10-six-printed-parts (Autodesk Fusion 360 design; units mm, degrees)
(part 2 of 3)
sketch "B Facet 180 Triangle 4" plane through (0, -75, 0) normal (0, -1, 0) x axis (-1, 0, 0)
  line L1 (124, -27.066) -> (60.9665, 27.066)
  line L2 (124, 27.066) -> (124, -27.066)
  line L3 (60.9665, 27.066) -> (124, 27.066)
  line L4 (120, -18.3583) -> (71.7639, 23.066)
  line L5 (120, 23.066) -> (120, -18.3583)
  line L6 (71.7639, 23.066) -> (120, 23.066)
  point P1 (0, 0)
  point P2 (60.9665, 27.066)
  point P3 (124, -27.066)
  point P4 (124, 27.066)
  dimension "d486" distance P1 P2 = 60.9665 (= "Linear Dimension-2")
  dimension "d487" distance P1 P2 = 27.066 (= "Linear Dimension-3")
  dimension "d488" distance P1 P3 = 124 (= "Linear Dimension-4")
  dimension "d489" distance P1 P3 = 27.066 (= "Linear Dimension-5")
  dimension "d490" distance P1 P4 = 124 (= "Linear Dimension-6")
  dimension "d491" distance P1 P4 = 27.066 (= "Linear Dimension-7")
  dimension "d492" = -4 (= "-memberWidth / 2")
extrude "Extrude15" cut sketch "B Facet 180 Triangle 4" profile of L5 L6 L4 against normal blind 4.7 (magnitude of "-( wall + 0.2 mm )")
fillet "Fillet5" radius 1.5 (= "apertureRadius")
work_plane "WorkPlane11" RotateAngle 135 ExtraOffset 0
work_plane "WorkPlane12" AlongDistance 75 (= "bodyWidth / 2") ExtraOffset 0
sketch "B Facet 225 Triangle 1" plane through (0, -53.033, -53.033) normal (0, -0.7071, -0.7071) x axis (1, 0, 0)
  line L1 (23.9949, -27.066) -> (62.2721, 27.066)
  line L2 (0.1814, 27.066) -> (23.9949, -27.066)
  line L3 (62.2721, 27.066) -> (0.1814, 27.066)
  line L4 (24.81, -18.9852) -> (54.5447, 23.066)
  line L5 (6.311, 23.066) -> (24.81, -18.9852)
  line L6 (54.5447, 23.066) -> (6.311, 23.066)
  point P1 (0, 0)
  point P2 (62.2721, 27.066)
  point P3 (23.9949, -27.066)
  point P4 (0.1814, 27.066)
  dimension "d501" distance P1 P2 = 62.2721 (= "Linear Dimension-2")
  dimension "d502" distance P1 P2 = 27.066 (= "Linear Dimension-3")
  dimension "d503" distance P1 P3 = 23.9949 (= "Linear Dimension-4")
  dimension "d504" distance P1 P3 = 27.066 (= "Linear Dimension-5")
  dimension "d505" distance P1 P4 = 0.1814 (= "Linear Dimension-6")
  dimension "d506" distance P1 P4 = 27.066 (= "Linear Dimension-7")
  dimension "d507" = 4 (= "memberWidth / 2")
extrude "Extrude16" cut sketch "B Facet 225 Triangle 1" profile of L5 L6 L4 against normal blind 4.7 (magnitude of "-( wall + 0.2 mm )")
sketch "B Facet 225 Triangle 2" plane through (0, -53.033, -53.033) normal (0, -0.7071, -0.7071) x axis (1, 0, 0)
  line L1 (0.1814, 27.066) -> (23.9949, -27.066)
  line L2 (-74.6684, -27.066) -> (0.1814, 27.066)
  line L3 (23.9949, -27.066) -> (-74.6684, -27.066)
  line L4 (-1.4863, 20.9235) -> (17.8653, -23.066)
  line L5 (-62.3117, -23.066) -> (-1.4863, 20.9235)
  line L6 (17.8653, -23.066) -> (-62.3117, -23.066)
  point P1 (0, 0)
  point P2 (23.9949, -27.066)
  point P3 (0.1814, 27.066)
  point P4 (-74.6684, -27.066)
  dimension "d510" distance P1 P2 = 23.9949 (= "Linear Dimension-2")
  dimension "d511" distance P1 P2 = 27.066 (= "Linear Dimension-3")
  dimension "d512" distance P1 P3 = 0.1814 (= "Linear Dimension-4")
  dimension "d513" distance P1 P3 = 27.066 (= "Linear Dimension-5")
  dimension "d514" distance P1 P4 = 74.6684 (= "Linear Dimension-6")
  dimension "d515" distance P1 P4 = 27.066 (= "Linear Dimension-7")
  dimension "d516" = -4 (= "-memberWidth / 2")
extrude "Extrude17" cut sketch "B Facet 225 Triangle 2" profile of L5 L6 L4 against normal blind 4.7 (magnitude of "-( wall + 0.2 mm )")
sketch "B Facet 225 Triangle 3" plane through (0, -53.033, -53.033) normal (0, -0.7071, -0.7071) x axis (1, 0, 0)
  line L1 (-74.6684, -27.066) -> (0.1814, 27.066)
  line L2 (-124, 27.066) -> (-74.6684, -27.066)
  line L3 (0.1814, 27.066) -> (-124, 27.066)
  line L4 (-74.1179, -21.7315) -> (-12.1753, 23.066)
  line L5 (-114.9429, 23.066) -> (-74.1179, -21.7315)
  line L6 (-12.1753, 23.066) -> (-114.9429, 23.066)
  point P1 (0, 0)
  point P2 (0.1814, 27.066)
  point P3 (-74.6684, -27.066)
  point P4 (-124, 27.066)
  dimension "d519" distance P1 P2 = 0.1814 (= "Linear Dimension-2")
  dimension "d520" distance P1 P2 = 27.066 (= "Linear Dimension-3")
  dimension "d521" distance P1 P3 = 74.6684 (= "Linear Dimension-4")
  dimension "d522" distance P1 P3 = 27.066 (= "Linear Dimension-5")
  dimension "d523" distance P1 P4 = 124 (= "Linear Dimension-6")
  dimension "d524" distance P1 P4 = 27.066 (= "Linear Dimension-7")
  dimension "d525" = 4 (= "memberWidth / 2")
extrude "Extrude18" cut sketch "B Facet 225 Triangle 3" profile of L5 L6 L4 against normal blind 4.7 (magnitude of "-( wall + 0.2 mm )")
sketch "B Facet 225 Triangle 4" plane through (0, -53.033, -53.033) normal (0, -0.7071, -0.7071) x axis (1, 0, 0)
  line L1 (-124, 27.066) -> (-74.6684, -27.066)
  line L2 (-124, -27.066) -> (-124, 27.066)
  line L3 (-74.6684, -27.066) -> (-124, -27.066)
  line L4 (-120, 16.7383) -> (-83.7255, -23.066)
  line L5 (-120, -23.066) -> (-120, 16.7383)
  line L6 (-83.7255, -23.066) -> (-120, -23.066)
  point P1 (0, 0)
  point P2 (-74.6684, -27.066)
  point P3 (-124, 27.066)
  point P4 (-124, -27.066)
  dimension "d528" distance P1 P2 = 74.6684 (= "Linear Dimension-2")
  dimension "d529" distance P1 P2 = 27.066 (= "Linear Dimension-3")
  dimension "d530" distance P1 P3 = 124 (= "Linear Dimension-4")
  dimension "d531" distance P1 P3 = 27.066 (= "Linear Dimension-5")
  dimension "d532" distance P1 P4 = 124 (= "Linear Dimension-6")
  dimension "d533" distance P1 P4 = 27.066 (= "Linear Dimension-7")
  dimension "d534" = -4 (= "-memberWidth / 2")
extrude "Extrude19" cut sketch "B Facet 225 Triangle 4" profile of L5 L6 L4 against normal blind 4.7 (magnitude of "-( wall + 0.2 mm )")
fillet "Fillet6" radius 1.5 (= "apertureRadius")
work_plane "WorkPlane13" RotateAngle 180 ExtraOffset 0
work_plane "WorkPlane14" AlongDistance 75 (= "bodyWidth / 2") ExtraOffset 0
sketch "B Facet 270 Triangle 1" plane through (0, 0, -75) normal (0, 0, -1) x axis (-1, 0, 0)
  line L1 (36.9655, 27.066) -> (-17.1665, -27.066)
  line L2 (53.4167, -27.066) -> (36.9655, 27.066)
  line L3 (-17.1665, -27.066) -> (53.4167, -27.066)
  line L4 (35.0777, 19.5214) -> (-7.5097, -23.066)
  line L5 (48.0205, -23.066) -> (35.0777, 19.5214)
  line L6 (-7.5097, -23.066) -> (48.0205, -23.066)
  point P1 (0, 0)
  point P2 (-17.1665, -27.066)
  point P3 (36.9655, 27.066)
  point P4 (53.4167, -27.066)
  dimension "d543" distance P1 P2 = 17.1665 (= "Linear Dimension-2")
  dimension "d544" distance P1 P2 = 27.066 (= "Linear Dimension-3")
  dimension "d545" distance P1 P3 = 36.9655 (= "Linear Dimension-4")
  dimension "d546" distance P1 P3 = 27.066 (= "Linear Dimension-5")
  dimension "d547" distance P1 P4 = 53.4167 (= "Linear Dimension-6")
  dimension "d548" distance P1 P4 = 27.066 (= "Linear Dimension-7")
  dimension "d549" = 4 (= "memberWidth / 2")
extrude "Extrude20" cut sketch "B Facet 270 Triangle 1" profile of L5 L6 L4 against normal blind 4.7 (magnitude of "-( wall + 0.2 mm )")
sketch "B Facet 270 Triangle 2" plane through (0, 0, -75) normal (0, 0, -1) x axis (-1, 0, 0)
  line L1 (53.4167, -27.066) -> (36.9655, 27.066)
  line L2 (124, 27.066) -> (53.4167, -27.066)
  line L3 (36.9655, 27.066) -> (124, 27.066)
  line L4 (55.5648, -20.3777) -> (42.3618, 23.066)
  line L5 (112.2115, 23.066) -> (55.5648, -20.3777)
  line L6 (42.3618, 23.066) -> (112.2115, 23.066)
  point P1 (0, 0)
  point P2 (36.9655, 27.066)
  point P3 (53.4167, -27.066)
  point P4 (124, 27.066)
  dimension "d552" distance P1 P2 = 36.9655 (= "Linear Dimension-2")
  dimension "d553" distance P1 P2 = 27.066 (= "Linear Dimension-3")
  dimension "d554" distance P1 P3 = 53.4167 (= "Linear Dimension-4")
  dimension "d555" distance P1 P3 = 27.066 (= "Linear Dimension-5")
  dimension "d556" distance P1 P4 = 124 (= "Linear Dimension-6")
  dimension "d557" distance P1 P4 = 27.066 (= "Linear Dimension-7")
  dimension "d558" = -4 (= "-memberWidth / 2")
extrude "Extrude21" cut sketch "B Facet 270 Triangle 2" profile of L5 L6 L4 against normal blind 4.7 (magnitude of "-( wall + 0.2 mm )")
sketch "B Facet 270 Triangle 3" plane through (0, 0, -75) normal (0, 0, -1) x axis (-1, 0, 0)
  line L1 (124, 27.066) -> (53.4167, -27.066)
  line L2 (124, -27.066) -> (124, 27.066)
  line L3 (53.4167, -27.066) -> (124, -27.066)
  line L4 (120, 18.9574) -> (65.2053, -23.066)
  line L5 (120, -23.066) -> (120, 18.9574)
  line L6 (65.2053, -23.066) -> (120, -23.066)
  point P1 (0, 0)
  point P2 (53.4167, -27.066)
  point P3 (124, 27.066)
  point P4 (124, -27.066)
  dimension "d561" distance P1 P2 = 53.4167 (= "Linear Dimension-2")
  dimension "d562" distance P1 P2 = 27.066 (= "Linear Dimension-3")
  dimension "d563" distance P1 P3 = 124 (= "Linear Dimension-4")
  dimension "d564" distance P1 P3 = 27.066 (= "Linear Dimension-5")
  dimension "d565" distance P1 P4 = 124 (= "Linear Dimension-6")
  dimension "d566" distance P1 P4 = 27.066 (= "Linear Dimension-7")
  dimension "d567" = 4 (= "memberWidth / 2")
extrude "Extrude22" cut sketch "B Facet 270 Triangle 3" profile of L5 L6 L4 against normal blind 4.7 (magnitude of "-( wall + 0.2 mm )")
fillet "Fillet7" radius 1.5 (= "apertureRadius")
work_plane "WorkPlane15" RotateAngle 225 ExtraOffset 0
work_plane "WorkPlane16" AlongDistance 75 (= "bodyWidth / 2") ExtraOffset 0
sketch "B Facet 315 Triangle 1" plane through (0, 53.033, -53.033) normal (0, 0.7071, -0.7071) x axis (1, 0, 0)
  line L1 (-82.0711, -27.066) -> (-43.7939, 27.066)
  line L2 (-124, 27.066) -> (-82.0711, -27.066)
  line L3 (-43.7939, 27.066) -> (-124, 27.066)
  line L4 (-82.2175, -20.3449) -> (-51.5213, 23.066)
  line L5 (-115.8422, 23.066) -> (-82.2175, -20.3449)
  line L6 (-51.5213, 23.066) -> (-115.8422, 23.066)
  point P1 (0, 0)
  point P2 (-43.7939, 27.066)
  point P3 (-82.0711, -27.066)
  point P4 (-124, 27.066)
  dimension "d576" distance P1 P2 = 43.7939 (= "Linear Dimension-2")
  dimension "d577" distance P1 P2 = 27.066 (= "Linear Dimension-3")
  dimension "d578" distance P1 P3 = 82.0711 (= "Linear Dimension-4")
  dimension "d579" distance P1 P3 = 27.066 (= "Linear Dimension-5")
  dimension "d580" distance P1 P4 = 124 (= "Linear Dimension-6")
  dimension "d581" distance P1 P4 = 27.066 (= "Linear Dimension-7")
  dimension "d582" = 4 (= "memberWidth / 2")
extrude "Extrude23" cut sketch "B Facet 315 Triangle 1" profile of L5 L6 L4 against normal blind 4.7 (magnitude of "-( wall + 0.2 mm )")
sketch "B Facet 315 Triangle 2" plane through (0, 53.033, -53.033) normal (0, 0.7071, -0.7071) x axis (1, 0, 0)
  line L1 (-124, 27.066) -> (-82.0711, -27.066)
  line L2 (-124, -27.066) -> (-124, 27.066)
  line L3 (-82.0711, -27.066) -> (-124, -27.066)
  line L4 (-120, 15.3697) -> (-90.2289, -23.066)
  line L5 (-120, -23.066) -> (-120, 15.3697)
  line L6 (-90.2289, -23.066) -> (-120, -23.066)
  point P1 (0, 0)
  point P2 (-82.0711, -27.066)
  point P3 (-124, 27.066)
  point P4 (-124, -27.066)
  dimension "d585" distance P1 P2 = 82.0711 (= "Linear Dimension-2")
  dimension "d586" distance P1 P2 = 27.066 (= "Linear Dimension-3")
  dimension "d587" distance P1 P3 = 124 (= "Linear Dimension-4")
  dimension "d588" distance P1 P3 = 27.066 (= "Linear Dimension-5")
  dimension "d589" distance P1 P4 = 124 (= "Linear Dimension-6")
  dimension "d590" distance P1 P4 = 27.066 (= "Linear Dimension-7")
  dimension "d591" = -4 (= "-memberWidth / 2")
extrude "Extrude24" cut sketch "B Facet 315 Triangle 2" profile of L5 L6 L4 against normal blind 4.7 (magnitude of "-( wall + 0.2 mm )")
fillet "Fillet8" radius 1.5 (= "apertureRadius")
work_plane "WorkPlane17" AlongDistance 0.5 (= "qFront") ExtraOffset 0
sketch "A Central Carrier sketch" plane through (0.3536, 0.3536, 0) normal (0.7071, 0.7071, 0) x axis (0, 0, 1)
  circle C1 centre (0, 0) radius 26
  dimension "d598" diameter C1 = 52 (= "carrierOD")
extrude "Extrude25" new body sketch "A Central Carrier sketch" along normal blind 18 (= "spokeDepth")
work_plane "WorkPlane18" AlongDistance 0.5 (= "qFront") ExtraOffset 0
sketch "A Spoke 1 Profile" plane through (0.3536, 0.3536, 0) normal (0.7071, 0.7071, 0) x axis (0, 0, 1)
  line L1 (37.3643, -145.3579) -> (-4.7984, -1.4054)
  line L2 (46.9611, -142.547) -> (37.3643, -145.3579)
  line L3 (4.7984, 1.4054) -> (46.9611, -142.547)
  line L4 (-4.7984, -1.4054) -> (4.7984, 1.4054)
  point P1 (0, 0)
  point P2 (-4.7984, -1.4054)
  point P3 (37.3643, -145.3579)
  point P4 (46.9611, -142.547)
  point P5 (4.7984, 1.4054)
  dimension "d603" distance P1 P2 = 4.7984 (= "Linear Dimension-2")
  dimension "d604" distance P1 P2 = 1.4054 (= "Linear Dimension-3")
  dimension "d605" distance P1 P3 = 37.3643 (= "Linear Dimension-4")
  dimension "d606" distance P1 P3 = 145.3579 (= "Linear Dimension-5")
  dimension "d607" distance P1 P4 = 46.9611 (= "Linear Dimension-6")
  dimension "d608" distance P1 P4 = 142.547 (= "Linear Dimension-7")
  dimension "d609" distance P1 P5 = 4.7984 (= "Linear Dimension-8")
  dimension "d610" distance P1 P5 = 1.4054 (= "Linear Dimension-9")
extrude "Extrude26" add sketch "A Spoke 1 Profile" along normal blind 18 (= "spokeDepth")
sketch "A Spoke 2 Profile" plane through (0.3536, 0.3536, 0) normal (0.7071, 0.7071, 0) x axis (0, 0, 1)
  line L1 (126.9012, -80.1317) -> (-2.5272, -4.3143)
  line L2 (131.9557, -71.5031) -> (126.9012, -80.1317)
  line L3 (2.5272, 4.3143) -> (131.9557, -71.5031)
  line L4 (-2.5272, -4.3143) -> (2.5272, 4.3143)
  point P1 (0, 0)
  point P2 (-2.5272, -4.3143)
  point P3 (126.9012, -80.1317)
  point P4 (131.9557, -71.5031)
  point P5 (2.5272, 4.3143)
  dimension "d613" distance P1 P2 = 2.5272 (= "Linear Dimension-2")
  dimension "d614" distance P1 P2 = 4.3143 (= "Linear Dimension-3")
  dimension "d615" distance P1 P3 = 126.9012 (= "Linear Dimension-4")
  dimension "d616" distance P1 P3 = 80.1317 (= "Linear Dimension-5")
  dimension "d617" distance P1 P4 = 131.9557 (= "Linear Dimension-6")
  dimension "d618" distance P1 P4 = 71.5031 (= "Linear Dimension-7")
  dimension "d619" distance P1 P5 = 2.5272 (= "Linear Dimension-8")
  dimension "d620" distance P1 P5 = 4.3143 (= "Linear Dimension-9")
extrude "Extrude27" add sketch "A Spoke 2 Profile" along normal blind 18 (= "spokeDepth")
sketch "A Spoke 3 Profile" plane through (0.3536, 0.3536, 0) normal (0.7071, 0.7071, 0) x axis (0, 0, 1)
  line L1 (131.9557, 71.5031) -> (2.5272, -4.3143)
  line L2 (126.9012, 80.1317) -> (131.9557, 71.5031)
  line L3 (-2.5272, 4.3143) -> (126.9012, 80.1317)
  line L4 (2.5272, -4.3143) -> (-2.5272, 4.3143)
  point P1 (0, 0)
  point P2 (2.5272, -4.3143)
  point P3 (131.9557, 71.5031)
  point P4 (126.9012, 80.1317)
  point P5 (-2.5272, 4.3143)
  dimension "d623" distance P1 P2 = 2.5272 (= "Linear Dimension-2")
  dimension "d624" distance P1 P2 = 4.3143 (= "Linear Dimension-3")
  dimension "d625" distance P1 P3 = 131.9557 (= "Linear Dimension-4")
  dimension "d626" distance P1 P3 = 71.5031 (= "Linear Dimension-5")
  dimension "d627" distance P1 P4 = 126.9012 (= "Linear Dimension-6")
  dimension "d628" distance P1 P4 = 80.1317 (= "Linear Dimension-7")
  dimension "d629" distance P1 P5 = 2.5272 (= "Linear Dimension-8")
  dimension "d630" distance P1 P5 = 4.3143 (= "Linear Dimension-9")
extrude "Extrude28" add sketch "A Spoke 3 Profile" along normal blind 18 (= "spokeDepth")
sketch "A Spoke 4 Profile" plane through (0.3536, 0.3536, 0) normal (0.7071, 0.7071, 0) x axis (0, 0, 1)
  line L1 (46.9611, 142.547) -> (4.7984, -1.4054)
  line L2 (37.3643, 145.3579) -> (46.9611, 142.547)
  line L3 (-4.7984, 1.4054) -> (37.3643, 145.3579)
  line L4 (4.7984, -1.4054) -> (-4.7984, 1.4054)
  point P1 (0, 0)
  point P2 (4.7984, -1.4054)
  point P3 (46.9611, 142.547)
  point P4 (37.3643, 145.3579)
  point P5 (-4.7984, 1.4054)
  dimension "d633" distance P1 P2 = 4.7984 (= "Linear Dimension-2")
  dimension "d634" distance P1 P2 = 1.4054 (= "Linear Dimension-3")
  dimension "d635" distance P1 P3 = 46.9611 (= "Linear Dimension-4")
  dimension "d636" distance P1 P3 = 142.547 (= "Linear Dimension-5")
  dimension "d637" distance P1 P4 = 37.3643 (= "Linear Dimension-6")
  dimension "d638" distance P1 P4 = 145.3579 (= "Linear Dimension-7")
  dimension "d639" distance P1 P5 = 4.7984 (= "Linear Dimension-8")
  dimension "d640" distance P1 P5 = 1.4054 (= "Linear Dimension-9")
extrude "Extrude29" add sketch "A Spoke 4 Profile" along normal blind 18 (= "spokeDepth")
sketch "A Spoke 5 Profile" plane through (0.3536, 0.3536, 0) normal (0.7071, 0.7071, 0) x axis (0, 0, 1)
  line L1 (-37.3643, 145.3579) -> (4.7984, 1.4054)
  line L2 (-46.9611, 142.547) -> (-37.3643, 145.3579)
  line L3 (-4.7984, -1.4054) -> (-46.9611, 142.547)
  line L4 (4.7984, 1.4054) -> (-4.7984, -1.4054)
  point P1 (0, 0)
  point P2 (4.7984, 1.4054)
  point P3 (-37.3643, 145.3579)
  point P4 (-46.9611, 142.547)
  point P5 (-4.7984, -1.4054)
  dimension "d643" distance P1 P2 = 4.7984 (= "Linear Dimension-2")
  dimension "d644" distance P1 P2 = 1.4054 (= "Linear Dimension-3")
  dimension "d645" distance P1 P3 = 37.3643 (= "Linear Dimension-4")
  dimension "d646" distance P1 P3 = 145.3579 (= "Linear Dimension-5")
  dimension "d647" distance P1 P4 = 46.9611 (= "Linear Dimension-6")
  dimension "d648" distance P1 P4 = 142.547 (= "Linear Dimension-7")
  dimension "d649" distance P1 P5 = 4.7984 (= "Linear Dimension-8")
  dimension "d650" distance P1 P5 = 1.4054 (= "Linear Dimension-9")
extrude "Extrude30" add sketch "A Spoke 5 Profile" along normal blind 18 (= "spokeDepth")
sketch "A Spoke 6 Profile" plane through (0.3536, 0.3536, 0) normal (0.7071, 0.7071, 0) x axis (0, 0, 1)
  line L1 (-126.9012, 80.1317) -> (2.5272, 4.3143)
  line L2 (-131.9557, 71.5031) -> (-126.9012, 80.1317)
  line L3 (-2.5272, -4.3143) -> (-131.9557, 71.5031)
  line L4 (2.5272, 4.3143) -> (-2.5272, -4.3143)
  point P1 (0, 0)
  point P2 (2.5272, 4.3143)
  point P3 (-126.9012, 80.1317)
  point P4 (-131.9557, 71.5031)
  point P5 (-2.5272, -4.3143)
  dimension "d653" distance P1 P2 = 2.5272 (= "Linear Dimension-2")
  dimension "d654" distance P1 P2 = 4.3143 (= "Linear Dimension-3")
  dimension "d655" distance P1 P3 = 126.9012 (= "Linear Dimension-4")
  dimension "d656" distance P1 P3 = 80.1317 (= "Linear Dimension-5")
  dimension "d657" distance P1 P4 = 131.9557 (= "Linear Dimension-6")
  dimension "d658" distance P1 P4 = 71.5031 (= "Linear Dimension-7")
  dimension "d659" distance P1 P5 = 2.5272 (= "Linear Dimension-8")
  dimension "d660" distance P1 P5 = 4.3143 (= "Linear Dimension-9")
extrude "Extrude31" add sketch "A Spoke 6 Profile" along normal blind 18 (= "spokeDepth")
sketch "A Spoke 7 Profile" plane through (0.3536, 0.3536, 0) normal (0.7071, 0.7071, 0) x axis (0, 0, 1)
  line L1 (-131.9557, -71.5031) -> (-2.5272, 4.3143)
  line L2 (-126.9012, -80.1317) -> (-131.9557, -71.5031)
  line L3 (2.5272, -4.3143) -> (-126.9012, -80.1317)
  line L4 (-2.5272, 4.3143) -> (2.5272, -4.3143)
  point P1 (0, 0)
  point P2 (-2.5272, 4.3143)
  point P3 (-131.9557, -71.5031)
  point P4 (-126.9012, -80.1317)
  point P5 (2.5272, -4.3143)
  dimension "d663" distance P1 P2 = 2.5272 (= "Linear Dimension-2")
  dimension "d664" distance P1 P2 = 4.3143 (= "Linear Dimension-3")
  dimension "d665" distance P1 P3 = 131.9557 (= "Linear Dimension-4")
  dimension "d666" distance P1 P3 = 71.5031 (= "Linear Dimension-5")
  dimension "d667" distance P1 P4 = 126.9012 (= "Linear Dimension-6")
  dimension "d668" distance P1 P4 = 80.1317 (= "Linear Dimension-7")
  dimension "d669" distance P1 P5 = 2.5272 (= "Linear Dimension-8")
  dimension "d670" distance P1 P5 = 4.3143 (= "Linear Dimension-9")
extrude "Extrude32" add sketch "A Spoke 7 Profile" along normal blind 18 (= "spokeDepth")
sketch "A Spoke 8 Profile" plane through (0.3536, 0.3536, 0) normal (0.7071, 0.7071, 0) x axis (0, 0, 1)
  line L1 (-46.9611, -142.547) -> (-4.7984, 1.4054)
  line L2 (-37.3643, -145.3579) -> (-46.9611, -142.547)
  line L3 (4.7984, 1.4054) -> (-37.3643, -145.3579)
  line L4 (-4.7984, 1.4054) -> (4.7984, 1.4054)
  point P1 (0, 0)
  point P2 (-4.7984, 1.4054)
  point P3 (-46.9611, -142.547)
  point P4 (-37.3643, -145.3579)
  point P5 (4.7984, 1.4054)
  dimension "d673" distance P1 P2 = 4.7984 (= "Linear Dimension-2")
  dimension "d674" distance P1 P2 = 1.4054 (= "Linear Dimension-3")
  dimension "d675" distance P1 P3 = 46.9611 (= "Linear Dimension-4")
  dimension "d676" distance P1 P3 = 142.547 (= "Linear Dimension-5")
  dimension "d677" distance P1 P4 = 37.3643 (= "Linear Dimension-6")
  dimension "d678" distance P1 P4 = 145.3579 (= "Linear Dimension-7")
  dimension "d679" distance P1 P5 = 4.7984 (= "Linear Dimension-8")
  dimension "d680" distance P1 P5 = 1.4054 (= "Linear Dimension-9")
extrude "Extrude33" add sketch "A Spoke 8 Profile" along normal blind 18 (= "spokeDepth")
sketch "Spoke Outer Envelope" plane through (0, 0, 0) normal (1, 0, 0) x axis (0, 0, -1)
  line L1 (31.066, 75) -> (75, 31.066)
  line L2 (-31.066, 75) -> (31.066, 75)
  line L3 (-75, 31.066) -> (-31.066, 75)
  line L4 (-75, -31.066) -> (-75, 31.066)
  line L5 (-31.066, -75) -> (-75, -31.066)
  line L6 (31.066, -75) -> (-31.066, -75)
  line L7 (75, -31.066) -> (31.066, -75)
  line L8 (75, 31.066) -> (75, -31.066)
  point P1 (0, 0)
  point P10 (0, 0)
  point P3 (31.066, 75)
  point P8 (31.066, -75)
  coincident P1 P10
  horizontal L2
  dimension "d683" distance P3 P8 = 150 (= "bodyWidth")
extrude "Extrude34" sketch "Spoke Outer Envelope" distance 260 (= "bodyLength")
fillet "Fillet9" radius 1 (= "rootRadius")
work_plane "WorkPlane19" AlongDistance 10.6 (= "qFrontBack") ExtraOffset 0
sketch "A Rear Carrier Clearance sketch" plane through (7.4953, 7.4953, 0) normal (0.7071, 0.7071, 0) x axis (0, 0, 1)
  circle C1 centre (0, 0) radius 23
  dimension "d690" diameter C1 = 46 (= "rearCarrierClearance")
extrude "Extrude35" cut sketch "A Rear Carrier Clearance sketch" along normal blind 18 (= "spokeDepth")
work_plane "WorkPlane20" AlongDistance 0.5 (= "qFront") ExtraOffset 0
sketch "A Seal Relief sketch" plane through (0.3536, 0.3536, 0) normal (0.7071, 0.7071, 0) x axis (0, 0, 1)
  circle C1 centre (0, 0) radius 9.75
  dimension "d695" diameter C1 = 19.5 (= "raceRelief")
extrude "Extrude36" cut sketch "A Seal Relief sketch" along normal blind 10.1 (= "frontSeatDepth + shoulder")
work_plane "WorkPlane21" AlongDistance 0.5 (= "qFront") ExtraOffset 0
sketch "A Front Bearing Seat sketch" plane through (0.3536, 0.3536, 0) normal (0.7071, 0.7071, 0) x axis (0, 0, 1)
  circle C1 centre (0, 0) radius 11.1
  dimension "d700" diameter C1 = 22.2 (= "seatDiameter")
extrude "Extrude37" cut sketch "A Front Bearing Seat sketch" along normal blind 7.1 (= "frontSeatDepth")
work_plane "WorkPlane22" AlongDistance 0.5 (= "qFront") ExtraOffset 0
sketch "A Support Bolt seed" plane through (0.3536, 0.3536, 0) normal (0.7071, 0.7071, 0) x axis (0, 0, 1)
  line L1 (17, 0) -> (0, 0)
  circle C1 centre (17, 0) radius 1.65
  point P1 (0, 0)
  point P2 (17, 0)
  horizontal L1
  dimension "d705" distance P1 P2 = 17 (= "supportCircle / 2")
  dimension "d706" diameter C1 = 3.3 (= "m3Clearance")
extrude "Extrude38" cut sketch "A Support Bolt seed" profile of C1 along normal blind 10.1 (= "frontSeatDepth + shoulder")
circular_pattern "C-Pattern1" TotalAngle 360
work_plane "WorkPlane23" AlongDistance 0.5 (= "qFront") ExtraOffset 0
sketch "A Front Bearing Boss sketch" plane through (0.3536, 0.3536, 0) normal (0.7071, 0.7071, 0) x axis (0, 0, 1)
  circle C1 centre (0, 0) radius 22
  dimension "d713" diameter C1 = 44 (= "coreOD")
chamfer "Chamfer1" distance 0.4 (= "entryChamfer")
work_plane "WorkPlane24" AlongDistance 75 (= "bodyWidth / 2") ExtraOffset 0
sketch "A Collar Driver Corridors" plane through (0, 0, 75) normal (0, 0, 1) x axis (1, 0, 0)
  circle C1 centre (6.7175, 15.9099) radius 3
  circle C2 centre (15.9099, 6.7175) radius 3
  point P1 (0, 0)
  point P2 (6.7175, 15.9099)
  point P3 (15.9099, 6.7175)
  dimension "d717" distance P1 P2 = 6.7175 (= "abs(( 16 mm + ( -6.5 mm ) ) / sqrt(2))")
  dimension "d718" distance P1 P2 = 15.9099 (= "abs(( 16 mm - ( -6.5 mm ) ) / sqrt(2))")
  dimension "d719" diameter C1 = 6
  dimension "d720" distance P1 P3 = 15.9099 (= "abs(( 16 mm + ( 6.5 mm ) ) / sqrt(2))")
  dimension "d721" distance P1 P3 = 6.7175 (= "abs(( 16 mm - ( 6.5 mm ) ) / sqrt(2))")
  dimension "d722" diameter C2 = 6
extrude "Extrude39" cut sketch "A Collar Driver Corridors" against normal blind 75 (magnitude of "-( bodyWidth / 2 )")
work_plane "WorkPlane17" ExtraOffset 0
sketch "B Central Carrier sketch" plane through (-0.3536, -0.3536, 0) normal (0.7071, 0.7071, 0) x axis (0, 0, 1)
  circle C1 centre (0, 0) radius 38
  dimension "d727" diameter C1 = 76 (= "mountOD")
extrude "Extrude25" new body sketch "B Central Carrier sketch" no distance stored
work_plane "WorkPlane18" ExtraOffset 0
sketch "B Spoke 1 Profile" plane through (-0.3536, -0.3536, 0) normal (0.7071, 0.7071, 0) x axis (0, 0, 1)
  line L1 (37.3643, -145.3579) -> (-4.7984, -1.4054)
  line L2 (46.9611, -142.547) -> (37.3643, -145.3579)
  line L3 (4.7984, 1.4054) -> (46.9611, -142.547)
  line L4 (-4.7984, -1.4054) -> (4.7984, 1.4054)
  point P1 (0, 0)
  point P2 (-4.7984, -1.4054)
  point P3 (37.3643, -145.3579)
  point P4 (46.9611, -142.547)
  point P5 (4.7984, 1.4054)
  dimension "d732" distance P1 P2 = 4.7984 (= "Linear Dimension-2")
  dimension "d733" distance P1 P2 = 1.4054 (= "Linear Dimension-3")
  dimension "d734" distance P1 P3 = 37.3643 (= "Linear Dimension-4")
  dimension "d735" distance P1 P3 = 145.3579 (= "Linear Dimension-5")
  dimension "d736" distance P1 P4 = 46.9611 (= "Linear Dimension-6")
  dimension "d737" distance P1 P4 = 142.547 (= "Linear Dimension-7")
  dimension "d738" distance P1 P5 = 4.7984 (= "Linear Dimension-8")
  dimension "d739" distance P1 P5 = 1.4054 (= "Linear Dimension-9")
extrude "Extrude26" add sketch "B Spoke 1 Profile" no distance stored
sketch "B Spoke 2 Profile" plane through (-0.3536, -0.3536, 0) normal (0.7071, 0.7071, 0) x axis (0, 0, 1)
  line L1 (126.9012, -80.1317) -> (-2.5272, -4.3143)
  line L2 (131.9557, -71.5031) -> (126.9012, -80.1317)
  line L3 (2.5272, 4.3143) -> (131.9557, -71.5031)
  line L4 (-2.5272, -4.3143) -> (2.5272, 4.3143)
  point P1 (0, 0)
  point P2 (-2.5272, -4.3143)
  point P3 (126.9012, -80.1317)
  point P4 (131.9557, -71.5031)
  point P5 (2.5272, 4.3143)
  dimension "d742" distance P1 P2 = 2.5272 (= "Linear Dimension-2")
  dimension "d743" distance P1 P2 = 4.3143 (= "Linear Dimension-3")
  dimension "d744" distance P1 P3 = 126.9012 (= "Linear Dimension-4")
  dimension "d745" distance P1 P3 = 80.1317 (= "Linear Dimension-5")
  dimension "d746" distance P1 P4 = 131.9557 (= "Linear Dimension-6")
  dimension "d747" distance P1 P4 = 71.5031 (= "Linear Dimension-7")
  dimension "d748" distance P1 P5 = 2.5272 (= "Linear Dimension-8")
  dimension "d749" distance P1 P5 = 4.3143 (= "Linear Dimension-9")
extrude "Extrude27" add sketch "B Spoke 2 Profile" no distance stored
sketch "B Spoke 3 Profile" plane through (-0.3536, -0.3536, 0) normal (0.7071, 0.7071, 0) x axis (0, 0, 1)
  line L1 (131.9557, 71.5031) -> (2.5272, -4.3143)
  line L2 (126.9012, 80.1317) -> (131.9557, 71.5031)
  line L3 (-2.5272, 4.3143) -> (126.9012, 80.1317)
  line L4 (2.5272, -4.3143) -> (-2.5272, 4.3143)
  point P1 (0, 0)
  point P2 (2.5272, -4.3143)
  point P3 (131.9557, 71.5031)
  point P4 (126.9012, 80.1317)
  point P5 (-2.5272, 4.3143)
  dimension "d752" distance P1 P2 = 2.5272 (= "Linear Dimension-2")
  dimension "d753" distance P1 P2 = 4.3143 (= "Linear Dimension-3")
  dimension "d754" distance P1 P3 = 131.9557 (= "Linear Dimension-4")
  dimension "d755" distance P1 P3 = 71.5031 (= "Linear Dimension-5")
  dimension "d756" distance P1 P4 = 126.9012 (= "Linear Dimension-6")
  dimension "d757" distance P1 P4 = 80.1317 (= "Linear Dimension-7")
  dimension "d758" distance P1 P5 = 2.5272 (= "Linear Dimension-8")
  dimension "d759" distance P1 P5 = 4.3143 (= "Linear Dimension-9")
extrude "Extrude28" add sketch "B Spoke 3 Profile" no distance stored
sketch "B Spoke 4 Profile" plane through (-0.3536, -0.3536, 0) normal (0.7071, 0.7071, 0) x axis (0, 0, 1)
  line L1 (46.9611, 142.547) -> (4.7984, -1.4054)
  line L2 (37.3643, 145.3579) -> (46.9611, 142.547)
  line L3 (-4.7984, 1.4054) -> (37.3643, 145.3579)
  line L4 (4.7984, -1.4054) -> (-4.7984, 1.4054)
  point P1 (0, 0)
  point P2 (4.7984, -1.4054)
  point P3 (46.9611, 142.547)
  point P4 (37.3643, 145.3579)
  point P5 (-4.7984, 1.4054)
  dimension "d762" distance P1 P2 = 4.7984 (= "Linear Dimension-2")
  dimension "d763" distance P1 P2 = 1.4054 (= "Linear Dimension-3")
  dimension "d764" distance P1 P3 = 46.9611 (= "Linear Dimension-4")
  dimension "d765" distance P1 P3 = 142.547 (= "Linear Dimension-5")
  dimension "d766" distance P1 P4 = 37.3643 (= "Linear Dimension-6")
  dimension "d767" distance P1 P4 = 145.3579 (= "Linear Dimension-7")
  dimension "d768" distance P1 P5 = 4.7984 (= "Linear Dimension-8")
  dimension "d769" distance P1 P5 = 1.4054 (= "Linear Dimension-9")
extrude "Extrude29" add sketch "B Spoke 4 Profile" no distance stored
sketch "B Spoke 5 Profile" plane through (-0.3536, -0.3536, 0) normal (0.7071, 0.7071, 0) x axis (0, 0, 1)
  line L1 (-37.3643, 145.3579) -> (4.7984, 1.4054)
  line L2 (-46.9611, 142.547) -> (-37.3643, 145.3579)
  line L3 (-4.7984, -1.4054) -> (-46.9611, 142.547)
  line L4 (4.7984, 1.4054) -> (-4.7984, -1.4054)
  point P1 (0, 0)
  point P2 (4.7984, 1.4054)
  point P3 (-37.3643, 145.3579)
  point P4 (-46.9611, 142.547)
  point P5 (-4.7984, -1.4054)
  dimension "d772" distance P1 P2 = 4.7984 (= "Linear Dimension-2")
  dimension "d773" distance P1 P2 = 1.4054 (= "Linear Dimension-3")
  dimension "d774" distance P1 P3 = 37.3643 (= "Linear Dimension-4")
  dimension "d775" distance P1 P3 = 145.3579 (= "Linear Dimension-5")
  dimension "d776" distance P1 P4 = 46.9611 (= "Linear Dimension-6")
  dimension "d777" distance P1 P4 = 142.547 (= "Linear Dimension-7")
  dimension "d778" distance P1 P5 = 4.7984 (= "Linear Dimension-8")
  dimension "d779" distance P1 P5 = 1.4054 (= "Linear Dimension-9")
extrude "Extrude30" add sketch "B Spoke 5 Profile" no distance stored
sketch "B Spoke 6 Profile" plane through (-0.3536, -0.3536, 0) normal (0.7071, 0.7071, 0) x axis (0, 0, 1)
  line L1 (-126.9012, 80.1317) -> (2.5272, 4.3143)
  line L2 (-131.9557, 71.5031) -> (-126.9012, 80.1317)
  line L3 (-2.5272, -4.3143) -> (-131.9557, 71.5031)
  line L4 (2.5272, 4.3143) -> (-2.5272, -4.3143)
  point P1 (0, 0)
  point P2 (2.5272, 4.3143)
  point P3 (-126.9012, 80.1317)
  point P4 (-131.9557, 71.5031)
  point P5 (-2.5272, -4.3143)
  dimension "d782" distance P1 P2 = 2.5272 (= "Linear Dimension-2")
  dimension "d783" distance P1 P2 = 4.3143 (= "Linear Dimension-3")
  dimension "d784" distance P1 P3 = 126.9012 (= "Linear Dimension-4")
  dimension "d785" distance P1 P3 = 80.1317 (= "Linear Dimension-5")
  dimension "d786" distance P1 P4 = 131.9557 (= "Linear Dimension-6")
  dimension "d787" distance P1 P4 = 71.5031 (= "Linear Dimension-7")
  dimension "d788" distance P1 P5 = 2.5272 (= "Linear Dimension-8")
  dimension "d789" distance P1 P5 = 4.3143 (= "Linear Dimension-9")
extrude "Extrude31" add sketch "B Spoke 6 Profile" no distance stored
sketch "B Spoke 7 Profile" plane through (-0.3536, -0.3536, 0) normal (0.7071, 0.7071, 0) x axis (0, 0, 1)
  line L1 (-131.9557, -71.5031) -> (-2.5272, 4.3143)
  line L2 (-126.9012, -80.1317) -> (-131.9557, -71.5031)
  line L3 (2.5272, -4.3143) -> (-126.9012, -80.1317)
  line L4 (-2.5272, 4.3143) -> (2.5272, -4.3143)
  point P1 (0, 0)
  point P2 (-2.5272, 4.3143)
  point P3 (-131.9557, -71.5031)
  point P4 (-126.9012, -80.1317)
  point P5 (2.5272, -4.3143)
  dimension "d792" distance P1 P2 = 2.5272 (= "Linear Dimension-2")
  dimension "d793" distance P1 P2 = 4.3143 (= "Linear Dimension-3")
  dimension "d794" distance P1 P3 = 131.9557 (= "Linear Dimension-4")
  dimension "d795" distance P1 P3 = 71.5031 (= "Linear Dimension-5")
  dimension "d796" distance P1 P4 = 126.9012 (= "Linear Dimension-6")
  dimension "d797" distance P1 P4 = 80.1317 (= "Linear Dimension-7")
  dimension "d798" distance P1 P5 = 2.5272 (= "Linear Dimension-8")
  dimension "d799" distance P1 P5 = 4.3143 (= "Linear Dimension-9")
extrude "Extrude32" add sketch "B Spoke 7 Profile" no distance stored
sketch "B Spoke 8 Profile" plane through (-0.3536, -0.3536, 0) normal (0.7071, 0.7071, 0) x axis (0, 0, 1)
  line L1 (-46.9611, -142.547) -> (-4.7984, 1.4054)
  line L2 (-37.3643, -145.3579) -> (-46.9611, -142.547)
  line L3 (4.7984, 1.4054) -> (-37.3643, -145.3579)
  line L4 (-4.7984, 1.4054) -> (4.7984, 1.4054)
  point P1 (0, 0)
  point P2 (-4.7984, 1.4054)
  point P3 (-46.9611, -142.547)
  point P4 (-37.3643, -145.3579)
  point P5 (4.7984, 1.4054)
  dimension "d802" distance P1 P2 = 4.7984 (= "Linear Dimension-2")
  dimension "d803" distance P1 P2 = 1.4054 (= "Linear Dimension-3")
  dimension "d804" distance P1 P3 = 46.9611 (= "Linear Dimension-4")
  dimension "d805" distance P1 P3 = 142.547 (= "Linear Dimension-5")
  dimension "d806" distance P1 P4 = 37.3643 (= "Linear Dimension-6")
  dimension "d807" distance P1 P4 = 145.3579 (= "Linear Dimension-7")
  dimension "d808" distance P1 P5 = 4.7984 (= "Linear Dimension-8")
  dimension "d809" distance P1 P5 = 1.4054 (= "Linear Dimension-9")
extrude "Extrude33" add sketch "B Spoke 8 Profile" no distance stored
sketch "Spoke Outer Envelope" plane through (0, 0, 0) normal (1, 0, 0) x axis (0, 0, -1)
  line L1 (31.066, 75) -> (75, 31.066)
  line L2 (-31.066, 75) -> (31.066, 75)
  line L3 (-75, 31.066) -> (-31.066, 75)
  line L4 (-75, -31.066) -> (-75, 31.066)
  line L5 (-31.066, -75) -> (-75, -31.066)
  line L6 (31.066, -75) -> (-31.066, -75)
  line L7 (75, -31.066) -> (31.066, -75)
  line L8 (75, 31.066) -> (75, -31.066)
  point P1 (0, 0)
  point P10 (0, 0)
  point P3 (31.066, 75)
  point P8 (31.066, -75)
  coincident P1 P10
  horizontal L2
  dimension "d812" distance P3 P8 = 150 (= "bodyWidth")
extrude "Extrude34" sketch "Spoke Outer Envelope" distance 260 (= "bodyLength")
fillet "Fillet9" radius 1 (= "rootRadius")
work_plane "WorkPlane19" ExtraOffset 0
sketch "B Open Hub Cavity sketch" plane through (-0.3536, -0.3536, 0) normal (0.7071, 0.7071, 0) x axis (0, 0, 1)
  circle C1 centre (0, 0) radius 25.15
  dimension "d819" diameter C1 = 50.3 (= "mountOpening")
extrude "Extrude35" cut sketch "B Open Hub Cavity sketch" no distance stored
work_plane "WorkPlane20" ExtraOffset 0
sketch "B Four Mount Holes" plane through (-0.3536, -0.3536, 0) normal (0.7071, 0.7071, 0) x axis (0, 0, 1)
  circle C1 centre (22.6274, 22.6274) radius 2.15
  circle C2 centre (-22.6274, 22.6274) radius 2.15
  circle C3 centre (-22.6274, -22.6274) radius 2.15
  circle C4 centre (22.6274, -22.6274) radius 2.15
  point P1 (0, 0)
  point P2 (22.6274, 22.6274)
  point P3 (-22.6274, 22.6274)
  point P4 (-22.6274, -22.6274)
  point P5 (22.6274, -22.6274)
  dimension "d824" distance P1 P2 = 22.6274 (= "abs(mountCircle / ( 2 * sqrt(2) ))")
  dimension "d825" distance P1 P2 = 22.6274 (= "abs(mountCircle / ( 2 * sqrt(2) ))")
  dimension "d826" diameter C1 = 4.3 (= "m4Clearance")
  dimension "d827" distance P1 P3 = 22.6274 (= "abs(-mountCircle / ( 2 * sqrt(2) ))")
  dimension "d828" distance P1 P3 = 22.6274 (= "abs(mountCircle / ( 2 * sqrt(2) ))")
  dimension "d829" diameter C2 = 4.3 (= "m4Clearance")
  dimension "d830" distance P1 P4 = 22.6274 (= "abs(-mountCircle / ( 2 * sqrt(2) ))")
  dimension "d831" distance P1 P4 = 22.6274 (= "abs(-mountCircle / ( 2 * sqrt(2) ))")
  dimension "d832" diameter C3 = 4.3 (= "m4Clearance")
  dimension "d833" distance P1 P5 = 22.6274 (= "abs(mountCircle / ( 2 * sqrt(2) ))")
  dimension "d834" distance P1 P5 = 22.6274 (= "abs(-mountCircle / ( 2 * sqrt(2) ))")
  dimension "d835" diameter C4 = 4.3 (= "m4Clearance")
extrude "Extrude36" cut sketch "B Four Mount Holes" no distance stored
sketch "B M4 Nut Pocket 1" plane through (-0.3536, -0.3536, 0) normal (0.7071, 0.7071, 0) x axis (0, 0, 1)
  line L1 (24.7059, 26.2274) -> (26.7843, 22.6274)
  line L2 (20.549, 26.2274) -> (24.7059, 26.2274)
  line L3 (18.4705, 22.6274) -> (20.549, 26.2274)
  line L4 (20.549, 19.0274) -> (18.4705, 22.6274)
  line L5 (24.7059, 19.0274) -> (20.549, 19.0274)
  line L6 (26.7843, 22.6274) -> (24.7059, 19.0274)
  circle C1 centre (22.6274, 22.6274) radius 4.1569
  point P3 (26.7843, 22.6274)
  point P4 (24.7059, 26.2274)
  point P5 (20.549, 26.2274)
  point P6 (18.4705, 22.6274)
  point P7 (20.549, 19.0274)
  point P8 (24.7059, 19.0274)
  point P1 (0, 0)
  point P2 (22.6274, 22.6274)
  coincident C1 P3
  coincident C1 P4
  coincident C1 P5
  coincident C1 P6
  coincident C1 P7
  coincident C1 P8
  equal L1 L2
  equal L1 L3
  equal L1 L4
  equal L1 L5
  equal L1 L6
  horizontal L2
  dimension "d838" distance P1 P2 = 22.6274 (= "abs(mountCircle / ( 2 * sqrt(2) ))")
  dimension "d839" distance P1 P2 = 22.6274 (= "abs(mountCircle / ( 2 * sqrt(2) ))")
  dimension "d840" diameter C1 = 8.3138 (= "2 * ( nutAF ) / sqrt(3)")
extrude "Extrude37" cut sketch "B M4 Nut Pocket 1" profile of L1 L2 L3 L4 L5 L6 no distance stored
sketch "B M4 Nut Pocket 2" plane through (-0.3536, -0.3536, 0) normal (0.7071, 0.7071, 0) x axis (0, 0, 1)
  line L1 (-20.549, 26.2274) -> (-18.4705, 22.6274)
  line L2 (-24.7059, 26.2274) -> (-20.549, 26.2274)
  line L3 (-26.7843, 22.6274) -> (-24.7059, 26.2274)
  line L4 (-24.7059, 19.0274) -> (-26.7843, 22.6274)
  line L5 (-20.549, 19.0274) -> (-24.7059, 19.0274)
  line L6 (-18.4705, 22.6274) -> (-20.549, 19.0274)
  circle C1 centre (-22.6274, 22.6274) radius 4.1569
  point P3 (-18.4705, 22.6274)
  point P4 (-20.549, 26.2274)
  point P5 (-24.7059, 26.2274)
  point P6 (-26.7843, 22.6274)
  point P7 (-24.7059, 19.0274)
  point P8 (-20.549, 19.0274)
  point P1 (0, 0)
  point P2 (-22.6274, 22.6274)
  coincident C1 P3
  coincident C1 P4
  coincident C1 P5
  coincident C1 P6
  coincident C1 P7
  coincident C1 P8
  equal L1 L2
  equal L1 L3
  equal L1 L4
  equal L1 L5
  equal L1 L6
  horizontal L2
  dimension "d843" distance P1 P2 = 22.6274 (= "abs(-mountCircle / ( 2 * sqrt(2) ))")
  dimension "d844" distance P1 P2 = 22.6274 (= "abs(mountCircle / ( 2 * sqrt(2) ))")
  dimension "d845" diameter C1 = 8.3138 (= "2 * ( nutAF ) / sqrt(3)")
extrude "Extrude38" cut sketch "B M4 Nut Pocket 2" profile of L1 L2 L3 L4 L5 L6 no distance stored
sketch "B M4 Nut Pocket 3" plane through (-0.3536, -0.3536, 0) normal (0.7071, 0.7071, 0) x axis (0, 0, 1)
  line L1 (-20.549, -19.0274) -> (-18.4705, -22.6274)
  line L2 (-24.7059, -19.0274) -> (-20.549, -19.0274)
  line L3 (-26.7843, -22.6274) -> (-24.7059, -19.0274)
  line L4 (-24.7059, -26.2274) -> (-26.7843, -22.6274)
  line L5 (-20.549, -26.2274) -> (-24.7059, -26.2274)
  line L6 (-18.4705, -22.6274) -> (-20.549, -26.2274)
  circle C1 centre (-22.6274, -22.6274) radius 4.1569
  point P3 (-18.4705, -22.6274)
  point P4 (-20.549, -19.0274)
  point P5 (-24.7059, -19.0274)
  point P6 (-26.7843, -22.6274)
  point P7 (-24.7059, -26.2274)
  point P8 (-20.549, -26.2274)
  point P1 (0, 0)
  point P2 (-22.6274, -22.6274)
  coincident C1 P3
  coincident C1 P4
  coincident C1 P5
  coincident C1 P6
  coincident C1 P7
  coincident C1 P8
  equal L1 L2
  equal L1 L3
  equal L1 L4
  equal L1 L5
  equal L1 L6
  horizontal L2
  dimension "d848" distance P1 P2 = 22.6274 (= "abs(-mountCircle / ( 2 * sqrt(2) ))")
  dimension "d849" distance P1 P2 = 22.6274 (= "abs(-mountCircle / ( 2 * sqrt(2) ))")
  dimension "d850" diameter C1 = 8.3138 (= "2 * ( nutAF ) / sqrt(3)")
extrude "Extrude39" cut sketch "B M4 Nut Pocket 3" profile of L1 L2 L3 L4 L5 L6 no distance stored
sketch "B M4 Nut Pocket 4" plane through (-0.3536, -0.3536, 0) normal (0.7071, 0.7071, 0) x axis (0, 0, 1)
  line L1 (24.7059, -19.0274) -> (26.7843, -22.6274)
  line L2 (20.549, -19.0274) -> (24.7059, -19.0274)
  line L3 (18.4705, -22.6274) -> (20.549, -19.0274)
  line L4 (20.549, -26.2274) -> (18.4705, -22.6274)
  line L5 (24.7059, -26.2274) -> (20.549, -26.2274)
  line L6 (26.7843, -22.6274) -> (24.7059, -26.2274)
  circle C1 centre (22.6274, -22.6274) radius 4.1569
  point P3 (26.7843, -22.6274)
  point P4 (24.7059, -19.0274)
  point P5 (20.549, -19.0274)
  point P6 (18.4705, -22.6274)
  point P7 (20.549, -26.2274)
  point P8 (24.7059, -26.2274)
  point P1 (0, 0)
  point P2 (22.6274, -22.6274)
  coincident C1 P3
  coincident C1 P4
  coincident C1 P5
  coincident C1 P6
  coincident C1 P7
  coincident C1 P8
  equal L1 L2
  equal L1 L3
  equal L1 L4
  equal L1 L5
  equal L1 L6
  horizontal L2
  dimension "d853" distance P1 P2 = 22.6274 (= "abs(mountCircle / ( 2 * sqrt(2) ))")
  dimension "d854" distance P1 P2 = 22.6274 (= "abs(-mountCircle / ( 2 * sqrt(2) ))")
  dimension "d855" diameter C1 = 8.3138 (= "2 * ( nutAF ) / sqrt(3)")
extrude "Extrude40" cut sketch "B M4 Nut Pocket 4" profile of L1 L2 L3 L4 L5 L6 no distance stored
sketch "B Hub Service Slots" plane through (0, 0, 0) normal (0, 0, 1) x axis (1, 0, 0)
  line L1 (-30.4056, -12.0208) -> (-14.8492, 3.5355)
  line L2 (-12.0208, -30.4056) -> (-30.4056, -12.0208)
  line L3 (3.5355, -14.8492) -> (-12.0208, -30.4056)
  line L4 (-14.8492, 3.5355) -> (3.5355, -14.8492)
  point P1 (0, 0)
  point P2 (-14.8492, 3.5355)
  point P3 (-30.4056, -12.0208)
  point P4 (-12.0208, -30.4056)
  point P5 (3.5355, -14.8492)
  dimension "d858" distance P1 P2 = 14.8492 (= "abs(( -8 mm - 13 mm ) / sqrt(2))")
  dimension "d859" distance P1 P2 = 3.5355 (= "abs(( -8 mm + 13 mm ) / sqrt(2))")
  dimension "d860" distance P1 P3 = 30.4056 (= "abs(( -30 mm - 13 mm ) / sqrt(2))")
  dimension "d861" distance P1 P3 = 12.0208 (= "abs(( -30 mm + 13 mm ) / sqrt(2))")
  dimension "d862" distance P1 P4 = 12.0208 (= "abs(( -30 mm + 13 mm ) / sqrt(2))")
  dimension "d863" distance P1 P4 = 30.4056 (= "abs(( -30 mm - 13 mm ) / sqrt(2))")
  dimension "d864" distance P1 P5 = 3.5355 (= "abs(( -8 mm + 13 mm ) / sqrt(2))")
  dimension "d865" distance P1 P5 = 14.8492 (= "abs(( -8 mm - 13 mm ) / sqrt(2))")
extrude "Extrude41" cut sketch "B Hub Service Slots" distance 76 (= "mountOD")
chamfer "Chamfer2" distance 0.3 (= "bedRelief")
chamfer "Chamfer3" distance 0.5 (= "tubeCornerChamfer")
chamfer "Chamfer4" sketch "A Facet 135 Triangle 1" distance 0.3 (= "tubeRimChamfer")
work_plane "WorkPlane25" RotateAngle 0 ExtraOffset 0
work_plane "WorkPlane26" AlongDistance 75 (= "bodyWidth / 2") ExtraOffset 0
sketch "A End Cord Port" plane through (0, 0, 75) normal (0, 0, 1) x axis (1, 0, 0)
  line L1 (125, 0) -> (0, 0)
  circle C1 centre (125, 0) radius 2.25
  point P1 (0, 0)
  point P2 (125, 0)
  horizontal L1
  dimension "d875" distance P1 P2 = 125 (= "abs(( 1 ) * ( ( 1 ) * cordStation ) + ( 0 ) * ( 0 mm ))")
  dimension "d876" diameter C1 = 4.5
extrude "Extrude40" cut sketch "A End Cord Port" profile of C1 no distance stored
chamfer "Chamfer5" distance 0.3 (= "bedRelief")
work_plane "WorkPlane27" RotateAngle 180 ExtraOffset 0
work_plane "WorkPlane28" AlongDistance 75 (= "bodyWidth / 2") ExtraOffset 0
sketch "A End Cord Port (1)" plane through (0, 0, -75) normal (0, 0, -1) x axis (-1, 0, 0)
  line L1 (-125, 0) -> (0, 0)
  circle C1 centre (-125, 0) radius 2.25
  point P1 (0, 0)
  point P2 (-125, 0)
  horizontal L1
  dimension "d884" distance P1 P2 = 125 (= "abs(( -1 ) * ( ( 1 ) * cordStation ) + ( 0 ) * ( 0 mm ))")
  dimension "d885" diameter C1 = 4.5
extrude "Extrude41" cut sketch "A End Cord Port (1)" profile of C1 no distance stored
chamfer "Chamfer6" distance 0.3 (= "bedRelief")
chamfer "Chamfer1" distance 0.3 (= "bedRelief")
chamfer "Chamfer2" distance 0.5 (= "tubeCornerChamfer")
chamfer "Chamfer3" sketch "A Facet 135 Triangle 1" distance 0.3 (= "tubeRimChamfer")
work_plane "WorkPlane21" RotateAngle 0 ExtraOffset 0
work_plane "WorkPlane22" AlongDistance 75 (= "bodyWidth / 2") ExtraOffset 0
sketch "B End Cord Port" plane through (0, 0, 75) normal (0, 0, 1) x axis (1, 0, 0)
  line L1 (-125, 0) -> (0, 0)
  circle C1 centre (-125, 0) radius 2.25
  point P1 (0, 0)
  point P2 (-125, 0)
  horizontal L1
  dimension "d896" distance P1 P2 = 125 (= "abs(( 1 ) * ( ( -1 ) * cordStation ) + ( 0 ) * ( 0 mm ))")
  dimension "d897" diameter C1 = 4.5
extrude "Extrude42" cut sketch "B End Cord Port" profile of C1 no distance stored
chamfer "Chamfer4" distance 0.3 (= "bedRelief")
work_plane "WorkPlane23" RotateAngle 180 ExtraOffset 0
work_plane "WorkPlane24" AlongDistance 75 (= "bodyWidth / 2") ExtraOffset 0
sketch "B End Cord Port (1)" plane through (0, 0, -75) normal (0, 0, -1) x axis (-1, 0, 0)
  line L1 (125, 0) -> (0, 0)
  circle C1 centre (125, 0) radius 2.25
  point P1 (0, 0)
  point P2 (125, 0)
  horizontal L1
  dimension "d905" distance P1 P2 = 125 (= "abs(( -1 ) * ( ( -1 ) * cordStation ) + ( 0 ) * ( 0 mm ))")
  dimension "d906" diameter C1 = 4.5
extrude "Extrude43" cut sketch "B End Cord Port (1)" profile of C1 no distance stored
chamfer "Chamfer5" distance 0.3 (= "bedRelief")
work_plane "WorkPlane1" AlongDistance 22.6 (= "qRearBase") ExtraOffset 0
sketch "D Rear Holder Blank sketch" plane through (15.9806, 15.9806, 0) normal (0.7071, 0.7071, 0) x axis (0, 0, 1)
  circle C1 centre (0, 0) radius 22
  dimension "d912" diameter C1 = 44 (= "coreOD")
extrude "Extrude1" new body sketch "D Rear Holder Blank sketch" along normal blind 10.2 (= "shoulder + rearSeatDepth")
work_plane "WorkPlane2" AlongDistance 22.6 (= "qRearBase") ExtraOffset 0
sketch "D Seal Relief sketch" plane through (15.9806, 15.9806, 0) normal (0.7071, 0.7071, 0) x axis (0, 0, 1)
  circle C1 centre (0, 0) radius 9.75
  dimension "d917" diameter C1 = 19.5 (= "raceRelief")
extrude "Extrude2" cut sketch "D Seal Relief sketch" along normal blind 10.2 (= "shoulder + rearSeatDepth")
work_plane "WorkPlane3" AlongDistance 25.6 (= "qRearBearing") ExtraOffset 0
sketch "D Rear Bearing Seat sketch" plane through (18.1019, 18.1019, 0) normal (0.7071, 0.7071, 0) x axis (0, 0, 1)
  circle C1 centre (0, 0) radius 11.1
  dimension "d922" diameter C1 = 22.2 (= "seatDiameter")
extrude "Extrude3" cut sketch "D Rear Bearing Seat sketch" along normal blind 7.2 (= "rearSeatDepth")
work_plane "WorkPlane4" AlongDistance 22.6 (= "qRearBase") ExtraOffset 0
sketch "D Support Bolt seed" plane through (15.9806, 15.9806, 0) normal (0.7071, 0.7071, 0) x axis (0, 0, 1)
  line L1 (17, 0) -> (0, 0)
  circle C1 centre (17, 0) radius 1.65
  point P1 (0, 0)
  point P2 (17, 0)
  horizontal L1
  dimension "d927" distance P1 P2 = 17 (= "supportCircle / 2")
  dimension "d928" diameter C1 = 3.3 (= "m3Clearance")
extrude "Extrude4" cut sketch "D Support Bolt seed" profile of C1 along normal blind 10.2 (= "shoulder + rearSeatDepth")
circular_pattern "C-Pattern1" TotalAngle 360
chamfer "Chamfer1" distance 0.4 (= "entryChamfer")
chamfer "Chamfer2" distance 0.3 (= "bedRelief")
work_plane "WorkPlane1" AlongDistance -2.5 (= "qFront - capThickness") ExtraOffset 0
sketch "C Front Bearing Cap Ring sketch" plane through (-1.7678, -1.7678, 0) normal (0.7071, 0.7071, 0) x axis (0, 0, 1)
  circle C1 centre (0, 0) radius 22
  circle C2 centre (0, 0) radius 9.75
  dimension "d937" diameter C1 = 44 (= "coreOD")
  dimension "d938" diameter C2 = 19.5 (= "raceRelief")
extrude "Extrude1" new body sketch "C Front Bearing Cap Ring sketch" along normal blind 3 (= "capThickness")
work_plane "WorkPlane2" AlongDistance -2.5 (= "qFront - capThickness") ExtraOffset 0
sketch "C Front Bearing Cap Bolt seed" plane through (-1.7678, -1.7678, 0) normal (0.7071, 0.7071, 0) x axis (0, 0, 1)
  line L1 (17, 0) -> (0, 0)
  circle C1 centre (17, 0) radius 1.65
  point P1 (0, 0)
  point P2 (17, 0)
  horizontal L1
  dimension "d943" distance P1 P2 = 17 (= "supportCircle / 2")
  dimension "d944" diameter C1 = 3.3 (= "m3Clearance")
extrude "Extrude2" cut sketch "C Front Bearing Cap Bolt seed" profile of C1 along normal blind 3 (= "capThickness")
circular_pattern "C-Pattern1" TotalAngle 360
chamfer "Chamfer1" distance 0.3 (= "bedRelief")
work_plane "WorkPlane1" AlongDistance 32.8 (= "qRearEnd") ExtraOffset 0
sketch "E Rear Bearing Cap Ring sketch" plane through (23.1931, 23.1931, 0) normal (0.7071, 0.7071, 0) x axis (0, 0, 1)
  circle C1 centre (0, 0) radius 22
  circle C2 centre (0, 0) radius 9.75
  dimension "d952" diameter C1 = 44 (= "coreOD")
  dimension "d953" diameter C2 = 19.5 (= "raceRelief")
extrude "Extrude1" new body sketch "E Rear Bearing Cap Ring sketch" along normal blind 3 (= "capThickness")
work_plane "WorkPlane2" AlongDistance 32.8 (= "qRearEnd") ExtraOffset 0
sketch "E Rear Bearing Cap Bolt seed" plane through (23.1931, 23.1931, 0) normal (0.7071, 0.7071, 0) x axis (0, 0, 1)
  line L1 (17, 0) -> (0, 0)
  circle C1 centre (17, 0) radius 1.65
  point P1 (0, 0)
  point P2 (17, 0)
  horizontal L1
  dimension "d958" distance P1 P2 = 17 (= "supportCircle / 2")
  dimension "d959" diameter C1 = 3.3 (= "m3Clearance")
extrude "Extrude2" cut sketch "E Rear Bearing Cap Bolt seed" profile of C1 along normal blind 3 (= "capThickness")
circular_pattern "C-Pattern1" TotalAngle 360
chamfer "Chamfer1" distance 0.3 (= "bedRelief")
work_plane "WorkPlane1" AlongDistance -29 (= "hubFace - adapterThickness") ExtraOffset 0
sketch "F Adapter Flange sketch" plane through (-20.5061, -20.5061, 0) normal (0.7071, 0.7071, 0) x axis (0, 0, 1)
  circle C1 centre (0, 0) radius 38
  dimension "d967" diameter C1 = 76 (= "mountOD")
extrude "Extrude1" new body sketch "F Adapter Flange sketch" along normal blind 6 (= "adapterThickness")
work_plane "WorkPlane2" AlongDistance -23 (= "hubFace") ExtraOffset 0
sketch "F Centering Pilot sketch" plane through (-16.2635, -16.2635, 0) normal (0.7071, 0.7071, 0) x axis (0, 0, 1)
  circle C1 centre (0, 0) radius 25
  circle C2 centre (0, 0) radius 17
  dimension "d972" diameter C1 = 50 (= "pilotDiameter")
  dimension "d973" diameter C2 = 34 (= "pilotInside")
extrude "Extrude2" add sketch "F Centering Pilot sketch" along normal blind 2 (= "pilotHeight")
